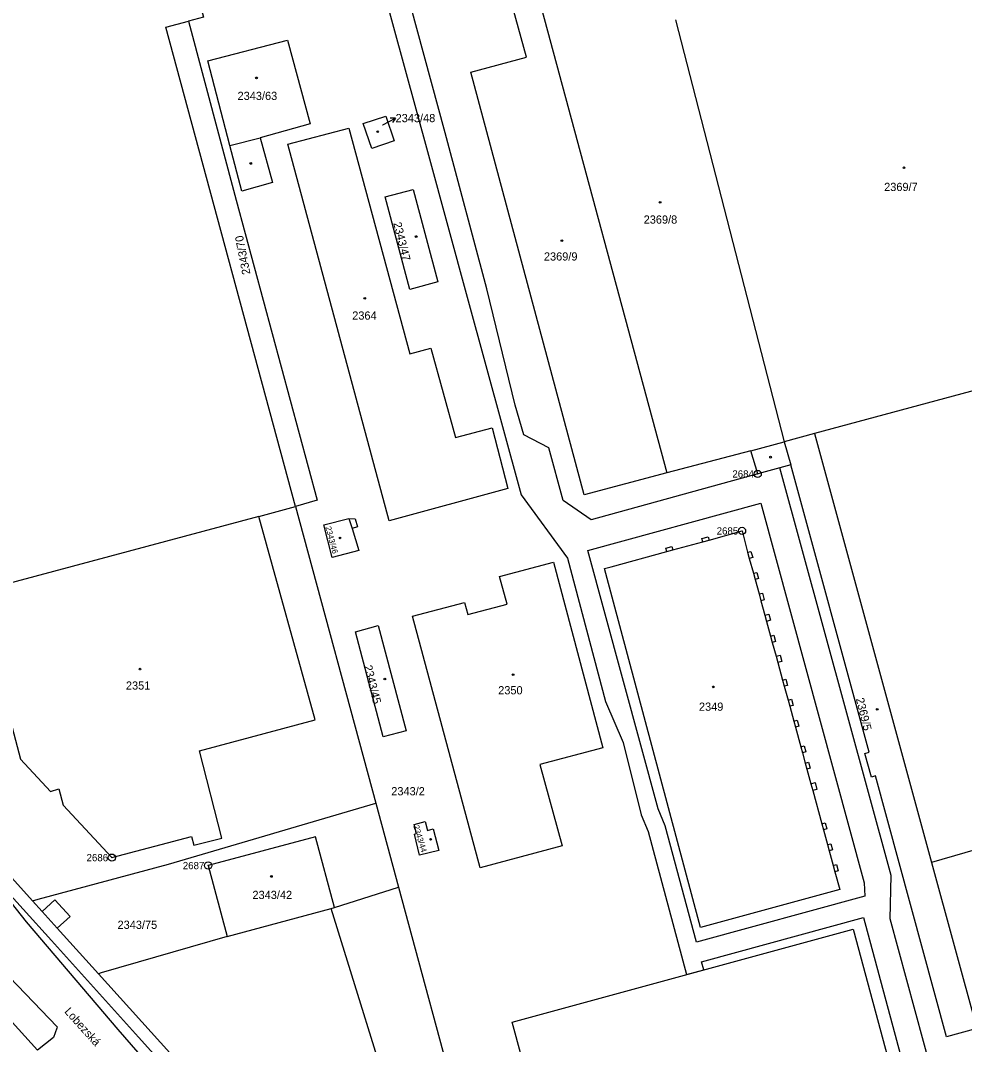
# Model space of a CAD drawing. Extents: x -821458 to -820266, y -1071458 to -1069826.
# Drawn here: x -821186.2 to -820990.7, y -1070550.7 to -1070338.6 of the extents above; entities that cross this region are included whole.
import ezdxf

# ---------------------------------------------------------------- set-up
doc = ezdxf.new("R2010")
doc.units = 0
for name, color, linetype in [('Vrstva 1', 7, 'Continuous'), ('Vrstva 13', 7, 'Continuous'), ('Vrstva 2', 7, 'Continuous'), ('Vrstva 4', 7, 'Continuous'), ('Vrstva 5', 7, 'Continuous'), ('Vrstva 7', 7, 'Continuous'), ('Vrstva 8', 7, 'Continuous')]:
    doc.layers.add(name, color=color, linetype=linetype)

msp = doc.modelspace()

# ---------------------------------------------------------------- linework, layer by layer
at = {"layer": 'Vrstva 1'}
for p, q in [((-821079.93, -1070329.99), (-821052.32, -1070432.3)), ((-821050.57, -1070338.41), (-821028.04, -1070425.85)), ((-820955.07, -1070406.16), (-821021.76, -1070424.16)), ((-821021.76, -1070424.16), (-821028.04, -1070425.85)), ((-821028.04, -1070425.85), (-821026.67, -1070430.62)), ((-821021.76, -1070424.16), (-820997.52, -1070512.98)), ((-821136.87, -1070441.33), (-821129.23, -1070439.26)), ((-821129.23, -1070439.26), (-821112.62, -1070500.74)), ((-821136.87, -1070441.33), (-821201.26, -1070458.54)), ((-821112.62, -1070500.74), (-821107.94, -1070518.09)), ((-820972.96, -1070505.96), (-820997.52, -1070512.98)), ((-820997.52, -1070512.98), (-820988.14, -1070547.37)), ((-821121.2, -1070522.34), (-821107.94, -1070518.09)), ((-821143.41, -1070528.32), (-821121.87, -1070522.52)), ((-821121.87, -1070522.52), (-821121.2, -1070522.34)), ((-821182.72, -1070551.87), (-821187.96, -1070546.11))]:
    msp.add_line(p, q, dxfattribs=at)
for points in [[(-821258.12, -1070332.09), (-821157.32, -1070304.65), (-821148.28, -1070337.88), (-821151.41, -1070338.71)], [(-821052.32, -1070432.3), (-821069.44, -1070436.81), (-821092.97, -1070349.27), (-821081.42, -1070346.17), (-821085.24, -1070332.07)], [(-821129.23, -1070439.26), (-821156.12, -1070339.95), (-821151.41, -1070338.71)], [(-821151.41, -1070338.71), (-821141.55, -1070375.76), (-821124.78, -1070437.96), (-821129.23, -1070439.26)], [(-821130.91, -1070342.66), (-821126.23, -1070359.99), (-821136.54, -1070362.89), (-821134.05, -1070372.16), (-821140.36, -1070373.95), (-821142.83, -1070364.44), (-821147.39, -1070346.93), (-821130.91, -1070342.66)], [(-821115.21, -1070359.92), (-821110.56, -1070358.35), (-821108.84, -1070363.52), (-821113.43, -1070365.08), (-821115.21, -1070359.92)], [(-821088.55, -1070422.98), (-821085.26, -1070435.51), (-821109.82, -1070442.23), (-821130.84, -1070364.2), (-821118.18, -1070360.85), (-821105.58, -1070407.6), (-821101.24, -1070406.43), (-821096.11, -1070424.96), (-821088.55, -1070422.98)], [(-821110.66, -1070375.13), (-821104.85, -1070373.59), (-821099.78, -1070392.73), (-821105.59, -1070394.27), (-821110.66, -1070375.13)], [(-821183.73, -1070520.92), (-821205.46, -1070496.83), (-821215, -1070486.68), (-821216.61, -1070484.97), (-821257.56, -1070440.79), (-821261.33, -1070436.77), (-821285.11, -1070412.22)], [(-821026.67, -1070430.62), (-821033.52, -1070432.51), (-821034.91, -1070427.71), (-821052.32, -1070432.3)], [(-820988.14, -1070547.37), (-820994.41, -1070549.1), (-821009.12, -1070495.08), (-821009.96, -1070495.32), (-821011.3, -1070490.42), (-821010.46, -1070490.16), (-821026.67, -1070430.62)], [(-821201.26, -1070458.54), (-821197.43, -1070472.66), (-821192.14, -1070481.93), (-821188.95, -1070481.1), (-821186.21, -1070491.62), (-821180.01, -1070498.29), (-821178.27, -1070497.75), (-821177.4, -1070501.1), (-821167.28, -1070512), (-821150.8, -1070507.61), (-821150.3, -1070509.44), (-821144.52, -1070507.96), (-821149.15, -1070489.84), (-821125.19, -1070483.48), (-821136.87, -1070441.33)], [(-821116.13, -1070448.38), (-821121.64, -1070449.83), (-821123.42, -1070443.06), (-821118.18, -1070441.73), (-821116.9, -1070441.8), (-821116.4, -1070443.44), (-821117.53, -1070443.8), (-821116.13, -1070448.38)], [(-821051.28, -1070447.56), (-821051.09, -1070448.25), (-821044.88, -1070446.56), (-821045.07, -1070445.86), (-821043.79, -1070445.51), (-821043.6, -1070446.21), (-821036.77, -1070444.31), (-821035.6, -1070448.74), (-821034.91, -1070448.55), (-821034.56, -1070449.82), (-821035.26, -1070450.01), (-821034.41, -1070453.09), (-821033.72, -1070452.9), (-821033.37, -1070454.16), (-821034.07, -1070454.35), (-821033.24, -1070457.37), (-821032.55, -1070457.18), (-821032.16, -1070458.61), (-821032.85, -1070458.8), (-821032.04, -1070461.78), (-821031.19, -1070461.55), (-821030.84, -1070462.83), (-821031.69, -1070463.06), (-821030.85, -1070466.13), (-821030.15, -1070465.94), (-821029.81, -1070467.21), (-821030.5, -1070467.4), (-821029.72, -1070470.29), (-821028.86, -1070470.05), (-821028.52, -1070471.33), (-821029.37, -1070471.56), (-821028.37, -1070475.22), (-821027.67, -1070475.03), (-821027.32, -1070476.31), (-821028.02, -1070476.5), (-821027.23, -1070479.36), (-821026.54, -1070479.17), (-821026.19, -1070480.45), (-821026.89, -1070480.64), (-821026.05, -1070483.71), (-821025.35, -1070483.52), (-821025, -1070484.79), (-821025.7, -1070484.98), (-821024.59, -1070489.03), (-821023.9, -1070488.84), (-821023.55, -1070490.11), (-821024.24, -1070490.3), (-821023.67, -1070492.41), (-821022.97, -1070492.22), (-821022.63, -1070493.49), (-821023.32, -1070493.68), (-821022.5, -1070496.68), (-821021.65, -1070496.45), (-821021.26, -1070497.87), (-821022.11, -1070498.1), (-821020.24, -1070504.97), (-821019.54, -1070504.78), (-821019.19, -1070506.06), (-821019.89, -1070506.25), (-821019.06, -1070509.3), (-821018.36, -1070509.11), (-821018.01, -1070510.4), (-821018.7, -1070510.59), (-821017.87, -1070513.64), (-821017.17, -1070513.45), (-821016.82, -1070514.75), (-821017.51, -1070514.93), (-821016.51, -1070518.6), (-821045.38, -1070526.49), (-821065.27, -1070452.12), (-821063.86, -1070451.74), (-821052.36, -1070448.6), (-821052.55, -1070447.9), (-821051.28, -1070447.56)], [(-821075.84, -1070450.75), (-821065.57, -1070489.23), (-821078.62, -1070492.71), (-821074.03, -1070509.57), (-821091.02, -1070514.13), (-821105.02, -1070462), (-821094.26, -1070459.11), (-821093.57, -1070461.65), (-821085.38, -1070459.46), (-821087.02, -1070453.77), (-821075.84, -1070450.75)], [(-821106.33, -1070485.74), (-821111.08, -1070487), (-821116.86, -1070465.21), (-821112.13, -1070463.89), (-821106.33, -1070485.74)], [(-821183.73, -1070520.92), (-821182.56, -1070520.6), (-821155.58, -1070513.32), (-821112.62, -1070500.74)], [(-821099.55, -1070510.49), (-821103.54, -1070511.51), (-821104.64, -1070507.12), (-821104.16, -1070506.99), (-821104.65, -1070505.14), (-821102.43, -1070504.53), (-821101.92, -1070506.38), (-821100.77, -1070506.06), (-821099.55, -1070510.49)], [(-821121.2, -1070522.34), (-821125.12, -1070507.68), (-821147.35, -1070513.64), (-821143.41, -1070528.32)], [(-821107.94, -1070518.09), (-821094.59, -1070567.44), (-821122.14, -1070589.18)], [(-821170.08, -1070536.04), (-821178.61, -1070526.59), (-821181.73, -1070523.14), (-821183.73, -1070520.92)], [(-821124.71, -1070586.33), (-821124.31, -1070585.93), (-821107.41, -1070569.05), (-821121.87, -1070522.52)], [(-821056.67, -1070614.26), (-821059.61, -1070607.98), (-821062.15, -1070602.39), (-821064.73, -1070592.29), (-821071.06, -1070593.87), (-821072.04, -1070590.14), (-821072.37, -1070590.25), (-821084.37, -1070546.1), (-821013.78, -1070526.79), (-820993.35, -1070602.46), (-821051.9, -1070618.43), (-821053.31, -1070613.12), (-821056.67, -1070614.26)], [(-821143.41, -1070528.32), (-821169.52, -1070535.88), (-821170.08, -1070536.04)], [(-821124.71, -1070586.33), (-821148.25, -1070560.23), (-821170.08, -1070536.04)]]:
    msp.add_lwpolyline(points, dxfattribs=at)
at = {"layer": 'Vrstva 13'}
for points in [[(-820997.43, -1070556.41), (-821006.07, -1070524.66), (-821005.9, -1070515.7), (-821028.94, -1070431.25), (-821033.52, -1070432.51), (-821068.02, -1070441.99), (-821073.83, -1070437.98), (-821076.8, -1070427.13), (-821081.99, -1070424.41), (-821083.77, -1070418.28), (-821089.59, -1070394.16), (-821098.28, -1070361.81), (-821119.79, -1070282.42), (-821142.78, -1070288.39), (-821177.68, -1070293.69), (-821201.2, -1070300.13)], [(-821238.1, -1070316.46), (-821161.41, -1070295.73), (-821141.61, -1070292.88), (-821127.93, -1070290.42), (-821121.69, -1070293.38), (-821101.69, -1070366.43), (-821093.68, -1070395.87), (-821082.52, -1070436.8), (-821072.94, -1070449.98), (-821065.02, -1070479.68), (-821061.41, -1070488.13), (-821057.64, -1070503.1), (-821056.19, -1070506.57), (-821048.26, -1070536.22), (-821044.69, -1070535.25), (-821045.15, -1070533.58), (-821011.58, -1070524.4), (-821001.61, -1070561.6)]]:
    msp.add_lwpolyline(points, dxfattribs=at)
msp.add_lwpolyline([(-821011.45, -1070517.22), (-821011.34, -1070519.99), (-821046.22, -1070529.52), (-821052.68, -1070505.39), (-821054.13, -1070501.92), (-821068.72, -1070448.4), (-821032.9, -1070438.58)], close=True, dxfattribs=at)
at = {"layer": 'Vrstva 4'}
for p, q in [((-821142.83, -1070364.44), (-821136.54, -1070362.89)), ((-821034.91, -1070427.71), (-821028.04, -1070425.85)), ((-821118.18, -1070441.73), (-821117.53, -1070443.8)), ((-821044.88, -1070446.56), (-821043.6, -1070446.21)), ((-821052.36, -1070448.6), (-821051.09, -1070448.25)), ((-821035.6, -1070448.74), (-821035.26, -1070450.01)), ((-821034.41, -1070453.09), (-821034.07, -1070454.35)), ((-821033.24, -1070457.37), (-821032.85, -1070458.8)), ((-821032.04, -1070461.78), (-821031.69, -1070463.06)), ((-821030.85, -1070466.13), (-821030.5, -1070467.4)), ((-821029.72, -1070470.29), (-821029.37, -1070471.56)), ((-821028.37, -1070475.22), (-821028.02, -1070476.5)), ((-821027.23, -1070479.36), (-821026.89, -1070480.64)), ((-821026.05, -1070483.71), (-821025.7, -1070484.98)), ((-821024.59, -1070489.03), (-821024.24, -1070490.3)), ((-821023.67, -1070492.41), (-821023.32, -1070493.68)), ((-821022.5, -1070496.68), (-821022.11, -1070498.1)), ((-821020.24, -1070504.97), (-821019.89, -1070506.25)), ((-821019.06, -1070509.3), (-821018.7, -1070510.59)), ((-821017.87, -1070513.64), (-821017.51, -1070514.93)), ((-821181.73, -1070523.14), (-821179.11, -1070520.73)), ((-821179.11, -1070520.73), (-821175.96, -1070524.16)), ((-821175.96, -1070524.16), (-821178.61, -1070526.59)), ((-821161.79, -1070549.17), (-821179.82, -1070529.19)), ((-821149.97, -1070565.91), (-821166.01, -1070547.63)), ((-821161.79, -1070549.17), (-821150.09, -1070562.08))]:
    msp.add_line(p, q, dxfattribs=at)
for points in [[(-821191.98, -1070516.44), (-821191.62, -1070516.15), (-821179.82, -1070529.19)], [(-821166.01, -1070547.63), (-821184.97, -1070525.27), (-821191.98, -1070516.44)], [(-821191.81, -1070533.38), (-821178.59, -1070547.05), (-821178.68, -1070547.3), (-821179.37, -1070549.25), (-821182.72, -1070551.87)]]:
    msp.add_lwpolyline(points, dxfattribs=at)
at = {"layer": 'Vrstva 5'}
for centre in [(-821137.33, -1070350.46), (-821112.23, -1070361.6), (-821138.52, -1070368.18), (-821003.22, -1070369.07), (-821053.73, -1070376.23), (-821104.26, -1070383.33), (-821074.07, -1070384.17), (-821114.91, -1070396.12), (-821030.86, -1070429.03), (-821120.03, -1070445.77), (-821161.46, -1070472.94), (-821110.75, -1070474.99), (-821084.18, -1070474.09), (-821042.72, -1070476.63), (-821008.77, -1070481.26), (-821101.26, -1070508.2), (-821134.24, -1070515.9)]:
    msp.add_circle(centre, 0.175, dxfattribs=at)
at = {"layer": 'Vrstva 7'}
for p, q in [((-821111.21, -1070360.18), (-821111.18, -1070360.17)), ((-821111.18, -1070360.17), (-821108.51, -1070358.81)), ((-821108.51, -1070358.81), (-821109.63, -1070358.82)), ((-821108.51, -1070358.81), (-821109.17, -1070359.71))]:
    msp.add_line(p, q, dxfattribs=at)
at = {"layer": 'Vrstva 8'}
for centre, radius in [((-821033.52, -1070432.51), 0.75), ((-821033.52, -1070432.51), 0.03), ((-821036.77, -1070444.31), 0.75), ((-821036.77, -1070444.31), 0.03), ((-821167.28, -1070512), 0.75), ((-821167.28, -1070512), 0.03), ((-821147.35, -1070513.64), 0.75), ((-821147.35, -1070513.64), 0.03)]:
    msp.add_circle(centre, radius, dxfattribs=at)

# ---------------------------------------------------------------- texts
at = {"layer": 'Vrstva 2'}
for s, p in [('2343/63', (-821141.26, -1070355.03)), ('2343/48', (-821108.52, -1070359.63)), ('2369/7', (-821007.33, -1070373.89)), ('2369/8', (-821057.14, -1070380.65)), ('2369/9', (-821077.8, -1070388.3)), ('2364', (-821117.51, -1070400.54)), ('2351', (-821164.38, -1070477.19)), ('2350', (-821087.27, -1070478.17)), ('2349', (-821045.69, -1070481.57)), ('2343/2', (-821109.42, -1070499.09)), ('2343/42', (-821138.17, -1070520.57)), ('2343/75', (-821166.12, -1070526.76))]:
    msp.add_text(s, height=1.7, dxfattribs=at).set_placement(p)
for s, height, rotation, p in [('2343/47', 1.7, 284, (-821109.02, -1070380.55)), ('2343/70', 1.7, 101, (-821138.58, -1070391.06)), ('2343/46', 1.2, 285, (-821123.08, -1070443.54)), ('2343/45', 1.7, 284, (-821115.1, -1070472.33)), ('2369/5', 1.7, 284, (-821013.21, -1070479.09)), ('2343/44', 1.2, 287, (-821104.86, -1070505.46))]:
    msp.add_text(s, height=height, rotation=rotation, dxfattribs=at).set_placement(p)
at = {"layer": 'Vrstva 7'}
msp.add_text('Lobezská', height=1.7, rotation=312, dxfattribs=at).set_placement((-821177.23, -1070543.97))
at = {"layer": 'Vrstva 8'}
for s, p in [('2684', (-821038.77, -1070433.26)), ('2685', (-821042.02, -1070445.06)), ('2686', (-821172.53, -1070512.75)), ('2687', (-821152.6, -1070514.39))]:
    msp.add_text(s, height=1.5, dxfattribs=at).set_placement(p)

doc.saveas('drawing.dxf')
